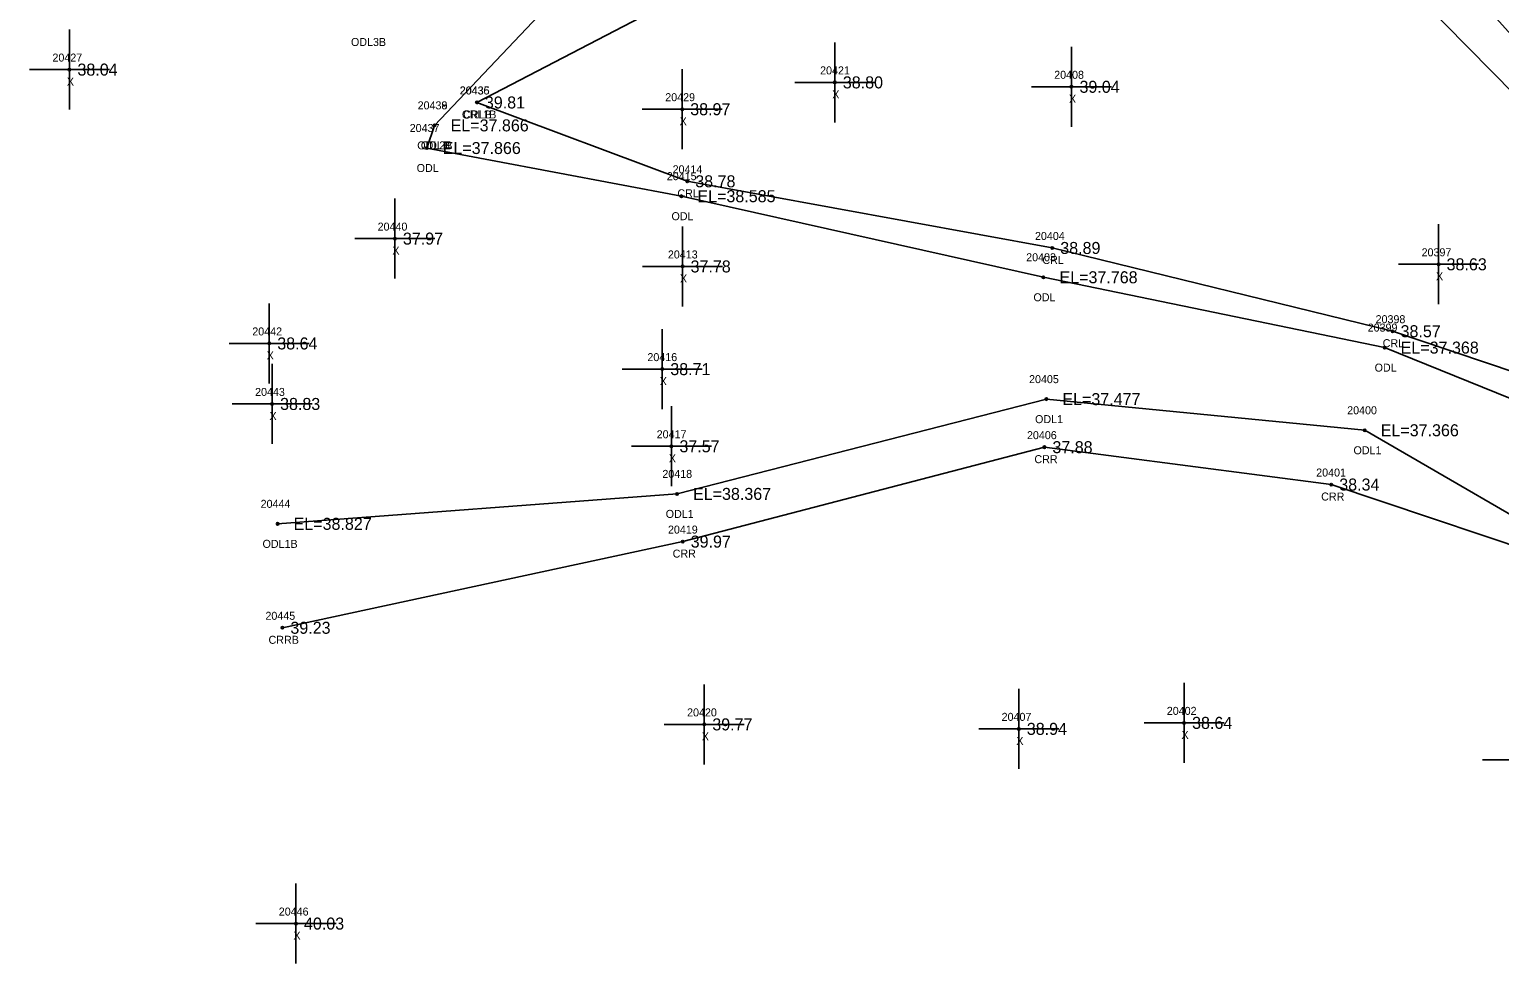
# Model space of a CAD drawing. Extents: x 2619569 to 2620117, y 784503 to 785150.
# Drawn here: x 2619568.7 to 2619752.4, y 784782.9 to 784899.6 of the extents above; entities that cross this region are included whole.
import ezdxf

# ---------------------------------------------------------------- set-up
doc = ezdxf.new("R2010")
doc.units = 0
for name, color, linetype in [('RD_EX_H2O', 7, 'Continuous'), ('RD_EX_H2O_txCode', 7, 'Continuous'), ('RD_EX_Misc', 7, 'Continuous'), ('RD_EX_Misc_txCode', 7, 'Continuous'), ('RD_EX_TX_H2O_ELEV', 7, 'Continuous'), ('RD_EX_TX_Misc_ELEV', 7, 'Continuous'), ('RD_SMD_Locator', 7, 'Continuous')]:
    doc.layers.add(name, color=color, linetype=linetype)

msp = doc.modelspace()

# ---------------------------------------------------------------- linework, layer by layer
at = {"layer": 'RD_EX_H2O'}
for points in [[(2619790.27, 784838.72), (2619782.87, 784866.71), (2619738.56, 784915.87), (2619703.69, 784928.29), (2619672.34, 784926.76), (2619648.41, 784918.34), (2619619.29, 784887.62)], [(2619773.83, 784850.15), (2619780.57, 784864.79), (2619733.81, 784912.21), (2619700.27, 784924.63), (2619672.07, 784923.77), (2619649.36, 784903.37), (2619624.57, 784890.48)], [(2619773.83, 784850.15), (2619738.99, 784861.9), (2619696.47, 784872.3), (2619650.86, 784880.63), (2619624.57, 784890.48)], [(2619790.27, 784838.72), (2619738, 784859.85), (2619695.37, 784868.64), (2619650.13, 784878.77), (2619618.3, 784884.79), (2619619.29, 784887.62)], [(2619816.45, 784807.13), (2619791.12, 784808.52), (2619763.98, 784833.06), (2619735.51, 784849.52), (2619695.73, 784853.41), (2619649.58, 784841.57), (2619599.67, 784837.83)], [(2619816.05, 784799.8), (2619788.01, 784803.33), (2619762.86, 784832.16), (2619731.33, 784842.74), (2619695.49, 784847.41), (2619650.29, 784835.61), (2619600.27, 784824.84)]]:
    msp.add_lwpolyline(points, dxfattribs=at)
at = {"layer": 'RD_EX_Misc'}
for p, q in [((2619573.66, 784889.59), (2619573.66, 784899.59)), ((2619669.3, 784887.99), (2619669.3, 784897.99)), ((2619698.87, 784887.44), (2619698.87, 784897.44)), ((2619568.66, 784894.59), (2619578.66, 784894.59)), ((2619650.23, 784884.64), (2619650.23, 784894.64)), ((2619664.3, 784892.99), (2619674.3, 784892.99)), ((2619693.87, 784892.44), (2619703.87, 784892.44)), ((2619645.23, 784889.64), (2619655.23, 784889.64)), ((2619614.33, 784868.47), (2619614.33, 784878.47)), ((2619650.27, 784864.99), (2619650.27, 784874.99)), ((2619744.74, 784865.26), (2619744.74, 784875.26)), ((2619609.33, 784873.47), (2619619.33, 784873.47)), ((2619645.27, 784869.99), (2619655.27, 784869.99)), ((2619739.74, 784870.26), (2619749.74, 784870.26)), ((2619598.63, 784855.37), (2619598.63, 784865.37)), ((2619647.74, 784852.16), (2619647.74, 784862.16)), ((2619593.63, 784860.37), (2619603.63, 784860.37)), ((2619598.98, 784847.81), (2619598.98, 784857.81)), ((2619642.74, 784857.16), (2619652.74, 784857.16)), ((2619593.98, 784852.81), (2619603.98, 784852.81)), ((2619648.88, 784842.52), (2619648.88, 784852.52)), ((2619643.88, 784847.52), (2619653.88, 784847.52)), ((2619652.99, 784807.77), (2619652.99, 784817.77)), ((2619692.29, 784807.21), (2619692.29, 784817.21)), ((2619712.94, 784807.96), (2619712.94, 784817.96)), ((2619707.94, 784812.96), (2619717.94, 784812.96)), ((2619647.99, 784812.77), (2619657.99, 784812.77)), ((2619687.29, 784812.21), (2619697.29, 784812.21)), ((2619750.22, 784808.36), (2619760.22, 784808.36)), ((2619601.97, 784782.88), (2619601.97, 784792.88)), ((2619596.97, 784787.88), (2619606.97, 784787.88))]:
    msp.add_line(p, q, dxfattribs=at)
at = {"layer": 'RD_SMD_Locator'}
for centre in [(2619573.66, 784894.59), (2619669.3, 784892.99), (2619698.87, 784892.44), (2619624.57, 784890.48), (2619624.57, 784890.48), (2619650.23, 784889.64), (2619619.29, 784887.62), (2619619.29, 784887.62), (2619618.3, 784884.79), (2619650.86, 784880.63), (2619650.13, 784878.77), (2619614.33, 784873.47), (2619696.47, 784872.3), (2619650.27, 784869.99), (2619744.74, 784870.26), (2619695.37, 784868.64), (2619738.99, 784861.9), (2619598.63, 784860.37), (2619738, 784859.85), (2619647.74, 784857.16), (2619695.73, 784853.41), (2619598.98, 784852.81), (2619735.51, 784849.52), (2619648.88, 784847.52), (2619695.49, 784847.41), (2619731.33, 784842.74), (2619649.58, 784841.57), (2619599.67, 784837.83), (2619650.29, 784835.61), (2619600.27, 784824.84), (2619712.94, 784812.96), (2619652.99, 784812.77), (2619692.29, 784812.21), (2619601.97, 784787.88)]:
    msp.add_circle(centre, 0.15, dxfattribs=at)

# ---------------------------------------------------------------- texts
at = {"layer": 'RD_EX_H2O_txCode'}
for s, p in [('ODL3B', (2619608.84, 784897.54)), ('20436', (2619622.42, 784891.48)), ('20435', (2619622.45, 784891.48)), ('20438', (2619617.17, 784889.62)), ('20439', (2619617.17, 784889.62)), ('CRL1B', (2619622.7, 784888.48)), ('CRLB', (2619622.86, 784888.48)), ('20437', (2619616.18, 784886.79)), ('ODL2B', (2619617.12, 784884.62)), ('ODLB', (2619617.57, 784884.62)), ('ODL', (2619617.05, 784881.79)), ('20415', (2619648.3, 784880.77)), ('20414', (2619649.03, 784881.63)), ('CRL', (2619649.63, 784878.63)), ('ODL', (2619648.89, 784875.77)), ('20404', (2619694.31, 784873.3)), ('20403', (2619693.21, 784870.64)), ('CRL', (2619695.24, 784870.3)), ('ODL', (2619694.12, 784865.64)), ('20399', (2619735.88, 784861.85)), ('20398', (2619736.87, 784862.9)), ('CRL', (2619737.76, 784859.9)), ('ODL', (2619736.75, 784856.85)), ('20405', (2619693.57, 784855.41)), ('20400', (2619733.32, 784851.52)), ('ODL1', (2619694.32, 784850.41)), ('20406', (2619693.31, 784848.41)), ('CRR', (2619694.24, 784845.41)), ('ODL1', (2619734.11, 784846.52)), ('20418', (2619647.75, 784843.57)), ('20401', (2619729.45, 784843.74)), ('20444', (2619597.55, 784839.83)), ('CRR', (2619730.07, 784840.74)), ('ODL1', (2619648.17, 784838.57)), ('20419', (2619648.45, 784836.61)), ('ODL1B', (2619597.79, 784834.83)), ('CRR', (2619649.04, 784833.61)), ('20445', (2619598.15, 784825.84)), ('CRRB', (2619598.54, 784822.84))]:
    msp.add_text(s, height=1, dxfattribs=at).set_placement(p)
at = {"layer": 'RD_EX_Misc_txCode'}
for s, p in [('20427', (2619571.54, 784895.59)), ('20421', (2619667.46, 784893.99)), ('20408', (2619696.71, 784893.44)), ('X', (2619573.34, 784892.59)), ('X', (2619668.98, 784890.99)), ('20429', (2619648.11, 784890.64)), ('X', (2619698.56, 784890.44)), ('X', (2619649.91, 784887.64)), ('20440', (2619612.17, 784874.47)), ('X', (2619614.01, 784871.47)), ('20413', (2619648.44, 784870.99)), ('20397', (2619742.62, 784871.26)), ('X', (2619649.95, 784867.99)), ('X', (2619744.42, 784868.26)), ('20442', (2619596.51, 784861.37)), ('X', (2619598.31, 784858.37)), ('20416', (2619645.88, 784858.16)), ('X', (2619647.42, 784855.16)), ('20443', (2619596.86, 784853.81)), ('X', (2619598.66, 784850.81)), ('20417', (2619647.04, 784848.52)), ('X', (2619648.56, 784845.52)), ('20402', (2619710.78, 784813.96)), ('20420', (2619650.84, 784813.77)), ('20407', (2619690.14, 784813.21)), ('X', (2619652.68, 784810.77)), ('X', (2619691.98, 784810.21)), ('X', (2619712.62, 784810.96)), ('20446', (2619599.82, 784788.88)), ('X', (2619601.65, 784785.88))]:
    msp.add_text(s, height=1, dxfattribs=at).set_placement(p)
at = {"layer": 'RD_EX_TX_H2O_ELEV'}
for s, p in [('39.81', (2619625.57, 784889.73)), ('39.81', (2619625.57, 784889.73)), ('EL=37.866', (2619621.29, 784886.87)), ('EL=37.866', (2619621.29, 784886.87)), ('EL=37.866', (2619620.3, 784884.04)), ('38.78', (2619651.86, 784879.88)), ('EL=38.585', (2619652.13, 784878.02)), ('38.89', (2619697.47, 784871.55)), ('EL=37.768', (2619697.37, 784867.89)), ('38.57', (2619739.99, 784861.15)), ('EL=37.368', (2619740, 784859.1)), ('EL=37.477', (2619697.73, 784852.66)), ('EL=37.366', (2619737.51, 784848.77)), ('37.88', (2619696.49, 784846.66)), ('38.34', (2619732.33, 784841.99)), ('EL=38.367', (2619651.58, 784840.82)), ('EL=38.827', (2619601.67, 784837.08)), ('39.97', (2619651.29, 784834.86)), ('39.23', (2619601.27, 784824.09))]:
    msp.add_text(s, height=1.5, dxfattribs=at).set_placement(p)
at = {"layer": 'RD_EX_TX_Misc_ELEV'}
for s, p in [('38.04', (2619574.66, 784893.84)), ('38.80', (2619670.3, 784892.24)), ('39.04', (2619699.87, 784891.69)), ('38.97', (2619651.23, 784888.89)), ('37.97', (2619615.33, 784872.72)), ('37.78', (2619651.27, 784869.24)), ('38.63', (2619745.74, 784869.51)), ('38.64', (2619599.63, 784859.62)), ('38.71', (2619648.74, 784856.41)), ('38.83', (2619599.98, 784852.06)), ('37.57', (2619649.88, 784846.77)), ('39.77', (2619653.99, 784812.02)), ('38.94', (2619693.29, 784811.46)), ('38.64', (2619713.94, 784812.21)), ('40.03', (2619602.97, 784787.13))]:
    msp.add_text(s, height=1.5, dxfattribs=at).set_placement(p)

doc.saveas('drawing.dxf')
